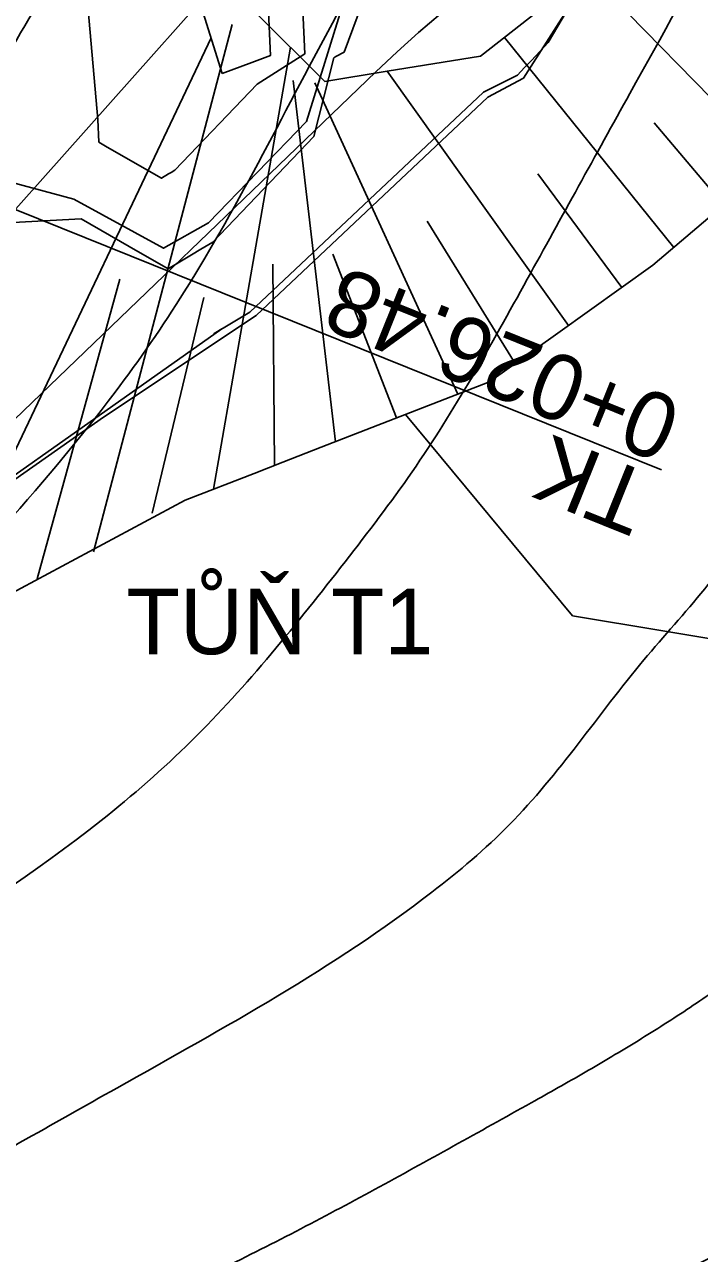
# Model space of a CAD drawing. Extents: x -564043 to -563833, y -1163561 to -1163412.
# Drawn here: x -563966.25 to -563953.38, y -1163509.03 to -1163485.61 of the extents above; entities that cross this region are included whole.
import ezdxf

# ---------------------------------------------------------------- set-up
doc = ezdxf.new("R2010")
doc.units = 0
for name, color, linetype in [('4', 7, 'Continuous'), ('5', 7, 'Continuous'), ('_popis staničení PH1', 7, 'Continuous'), ('Default', 7, 'Continuous'), ('Line', 7, 'Continuous'), ('Vrstva 24', 7, 'Continuous'), ('Vrstva 25', 7, 'Continuous'), ('Vrstva 26', 7, 'Continuous')]:
    doc.layers.add(name, color=color, linetype=linetype)

msp = doc.modelspace()

# ---------------------------------------------------------------- linework, layer by layer
for points in [[(-563976.663, -1163501.462), (-563964.742, -1163493.091), (-563961.829, -1163491.15), (-563957.41, -1163486.988), (-563956.735, -1163486.627), (-563953.281, -1163481.221), (-563953.993, -1163478.343), (-563957.796, -1163470.824), (-563957.81, -1163470.439), (-563957.835, -1163469.754), (-563958.239, -1163469.063), (-563958.187, -1163468.683), (-563959.529, -1163466.077), (-563960.166, -1163464.984), (-563964.31, -1163473.527), (-563966.903, -1163478.544), (-563968.406, -1163481.669), (-563970.316, -1163485.955), (-563973.278, -1163492.988), (-563976.735, -1163500.155), (-563977.161, -1163500.889), (-563977.363, -1163501.307)], [(-563962.125, -1163475.875), (-563962.765, -1163475.108), (-563963.856, -1163475.351), (-563965.212, -1163477.785), (-563966.919, -1163483.486), (-563967.557, -1163485.407), (-563967.871, -1163486.226), (-563967.716, -1163488.285), (-563965.306, -1163488.933), (-563963.594, -1163489.868), (-563962.736, -1163489.387), (-563960.869, -1163487.453), (-563959.333, -1163482.497), (-563959.613, -1163479.666)], [(-563962.48, -1163486.536), (-563961.911, -1163486.326), (-563961.553, -1163486.194), (-563961.747, -1163482.024), (-563961.878, -1163479.201), (-563962.246, -1163479.103), (-563962.794, -1163479.244), (-563962.818, -1163479.245), (-563963.128, -1163481.546), (-563962.901, -1163485.181)]]:
    msp.add_lwpolyline(points, close=True)
for points in [[(-563960.523, -1163486.688), (-563961.829, -1163485.385), (-563962.324, -1163483.708), (-563962.461, -1163482.584), (-563962.597, -1163481.459), (-563962.579, -1163480.501), (-563961.736, -1163479.195), (-563961.088, -1163479.165), (-563960.669, -1163479.145), (-563960.089, -1163479.118), (-563959.09, -1163479.072), (-563958.091, -1163479.026), (-563957.266, -1163478.987), (-563957.092, -1163478.979), (-563955.995, -1163480.274), (-563955.699, -1163482.25), (-563955.954, -1163483.392), (-563956.177, -1163485.128), (-563956.177, -1163485.128), (-563956.177, -1163485.128), (-563957.55, -1163486.21)], [(-563965.051, -1163485.101), (-563964.85, -1163487.418), (-563964.83, -1163487.847), (-563964.668, -1163487.941), (-563963.636, -1163488.535), (-563963.502, -1163488.454), (-563963.449, -1163488.423), (-563963.381, -1163488.382), (-563961.809, -1163486.742), (-563960.902, -1163486.164), (-563961.157, -1163480.663)], [(-563968.084, -1163484.934), (-563968.744, -1163486.445), (-563969.289, -1163489.534), (-563965.164, -1163489.309), (-563965.164, -1163489.309), (-563964.25, -1163489.835), (-563963.508, -1163490.263), (-563963.061, -1163489.994), (-563962.883, -1163489.889), (-563962.657, -1163489.751), (-563960.727, -1163487.738), (-563960.348, -1163486.241), (-563960.31, -1163486.212), (-563960.154, -1163486.129), (-563958.95, -1163482.892)], [(-563951.913, -1163488.197), (-563954.263, -1163490.192), (-563956.079, -1163491.487), (-563957.379, -1163492.414), (-563960.591, -1163493.664), (-563961.319, -1163493.948), (-563961.866, -1163494.161), (-563963.182, -1163494.674), (-563968.138, -1163497.33), (-563968.634, -1163497.596), (-563970.944, -1163498.688), (-563971.597, -1163498.997), (-563976.56, -1163501.343), (-563977.332, -1163501.295), (-563976.988, -1163500.693), (-563975.559, -1163498.192), (-563975.396, -1163497.906), (-563973.296, -1163494.084), (-563973.133, -1163493.747), (-563971.654, -1163490.682), (-563969.513, -1163486.248), (-563968.702, -1163484.611)], [(-563960.523, -1163486.688), (-563959.331, -1163486.495), (-563957.55, -1163486.21)], [(-563940.257, -1163499.457), (-563955.795, -1163496.878), (-563958.985, -1163493.039)]]:
    msp.add_lwpolyline(points)
at = {"layer": '5'}
msp.add_line((-563974.94, -1163501.303), (-563959.546, -1163486.507), dxfattribs=at)
msp.add_arc((-563942.222, -1163504.531), 25, 113.6313, 133.8653, dxfattribs=at)
at = {"layer": '_popis staničení PH1'}
msp.add_lwpolyline([(-563972.599, -1163486.649), (-563954.098, -1163494.096)], dxfattribs=at)
at = {"layer": 'Default'}
msp.add_lwpolyline([(-563953.444, -1163481.184), (-563956.263, -1163485.948), (-563956.577, -1163486.293), (-563956.711, -1163486.426), (-563956.848, -1163486.572), (-563957.497, -1163486.891), (-563961.953, -1163491.085), (-563962.333, -1163491.316), (-563962.631, -1163491.492), (-563962.482, -1163491.404), (-563976.56, -1163501.343)], dxfattribs=at)
at = {"layer": 'Line'}
for p, q in [((-563951.96, -1163488.236), (-563956.04, -1163484.057)), ((-563962.901, -1163485.181), (-563977.279, -1163501.298)), ((-563964.928, -1163495.656), (-563962.285, -1163485.606)), ((-563968.138, -1163497.33), (-563962.69, -1163485.858)), ((-563962.645, -1163494.465), (-563961.176, -1163486.037)), ((-563953.865, -1163489.855), (-563957.097, -1163485.853)), ((-563955.874, -1163491.341), (-563959.329, -1163486.494)), ((-563960.316, -1163493.557), (-563961.127, -1163486.674)), ((-563957.986, -1163492.65), (-563960.711, -1163486.719)), ((-563954.241, -1163487.481), (-563952.912, -1163489.046)), ((-563956.456, -1163488.453), (-563954.856, -1163490.615)), ((-563958.571, -1163489.355), (-563956.892, -1163492.066)), ((-563960.367, -1163489.982), (-563959.151, -1163493.104)), ((-563961.513, -1163490.172), (-563961.48, -1163494.011)), ((-563964.431, -1163490.456), (-563966.005, -1163496.172)), ((-563962.83, -1163490.808), (-563963.81, -1163494.918))]:
    msp.add_line(p, q, dxfattribs=at)
at = {"layer": 'Vrstva 24'}
for points in [[(-563978.297, -1163509.021), (-563978.261, -1163509.003), (-563973.613, -1163506.565), (-563973.263, -1163506.351), (-563972.852, -1163506.074), (-563964.784, -1163500.778), (-563963.064, -1163499.262), (-563960.133, -1163495.845), (-563958.857, -1163494.133), (-563956.661, -1163490.461), (-563954.703, -1163486.917), (-563951.017, -1163480.396), (-563950.659, -1163479.782), (-563950.563, -1163479.619)], [(-563978.949, -1163516.619), (-563975.171, -1163515.313), (-563974.108, -1163514.884), (-563972.002, -1163513.885), (-563969.907, -1163512.865), (-563967.813, -1163511.846), (-563965.709, -1163510.847), (-563964.325, -1163510.207), (-563962.597, -1163509.381), (-563961.075, -1163508.613), (-563959.57, -1163507.812), (-563958.075, -1163506.99), (-563956.583, -1163506.159), (-563955.558, -1163505.578), (-563954.547, -1163504.976), (-563953.555, -1163504.342), (-563952.588, -1163503.665), (-563951.319, -1163502.66), (-563950.112, -1163501.587), (-563949.038, -1163500.583), (-563947.98, -1163499.563), (-563946.918, -1163498.547), (-563945.835, -1163497.554), (-563945.703, -1163497.443), (-563945.609, -1163497.371), (-563945.171, -1163496.955), (-563943.72, -1163495.5)]]:
    msp.add_spline(points, degree=3, dxfattribs=at)
at = {"layer": 'Vrstva 25'}
msp.add_spline([(-563979.181, -1163499.008), (-563978.428, -1163498.506), (-563977.533, -1163497.79), (-563971.745, -1163492.882), (-563969.933, -1163491.157), (-563968.824, -1163489.747), (-563966.163, -1163485.494), (-563965.399, -1163484.181), (-563964.1, -1163481.868), (-563961.431, -1163477.021), (-563960.731, -1163475.725), (-563960.044, -1163474.189), (-563959.617, -1163472.641), (-563959.116, -1163469.866), (-563959.228, -1163469.046), (-563959.512, -1163468.326), (-563959.82, -1163467.638), (-563960.515, -1163466.313), (-563961.208, -1163465.1)], degree=3, dxfattribs=at)
at = {"layer": 'Vrstva 26'}
for points in [[(-563980.746, -1163506.255), (-563980.047, -1163505.928), (-563978.898, -1163505.186), (-563978.091, -1163504.559), (-563977.304, -1163503.908), (-563976.514, -1163503.264), (-563975.695, -1163502.656), (-563974.591, -1163501.929), (-563973.468, -1163501.232), (-563972.341, -1163500.538), (-563971.226, -1163499.825), (-563970.447, -1163499.268), (-563969.15, -1163497.951), (-563964.517, -1163492.611), (-563963.2, -1163490.7), (-563960.284, -1163485.41), (-563958.779, -1163482.786), (-563956.142, -1163478.307), (-563954.428, -1163475.228)], [(-563979.339, -1163513.451), (-563976.454, -1163512.115), (-563974.079, -1163510.944), (-563968.189, -1163507.943), (-563964.488, -1163505.88), (-563958.479, -1163502.145), (-563957, -1163500.857), (-563954.437, -1163497.718), (-563953.277, -1163496.363), (-563952.789, -1163495.73), (-563951.998, -1163494.583), (-563951.243, -1163493.409), (-563950.48, -1163492.242), (-563949.665, -1163491.113), (-563947.525, -1163488.408), (-563947.448, -1163488.312)], [(-563978.978, -1163519.771), (-563978.765, -1163519.704), (-563976.028, -1163518.79), (-563972.649, -1163517.594), (-563970.971, -1163516.964), (-563969.305, -1163516.304), (-563967.032, -1163515.3), (-563965.961, -1163514.798), (-563964.896, -1163514.286), (-563963.829, -1163513.774), (-563962.756, -1163513.276), (-563957.668, -1163511.196), (-563957.314, -1163511.075), (-563956.846, -1163510.894), (-563954.728, -1163509.895), (-563952.637, -1163508.844), (-563950.551, -1163507.783), (-563948.449, -1163506.755), (-563947.233, -1163506.198), (-563945.851, -1163505.471), (-563944.971, -1163504.882), (-563944.101, -1163504.279), (-563942.358, -1163503.079), (-563941.411, -1163502.449)]]:
    msp.add_spline(points, degree=3, dxfattribs=at)

# ---------------------------------------------------------------- texts
at = {"layer": '4'}
msp.add_text('TŮŇ T1', height=1.25, rotation=360, dxfattribs=at).set_placement((-563964.304, -1163497.609))
at = {"layer": '_popis staničení PH1'}
for s, p in [('0+026.48', (-563953.653, -1163492.818)), ('TK ', (-563954.213, -1163494.21))]:
    msp.add_text(s, height=1.25, rotation=158.0764, dxfattribs=at).set_placement(p)

doc.saveas('drawing.dxf')
